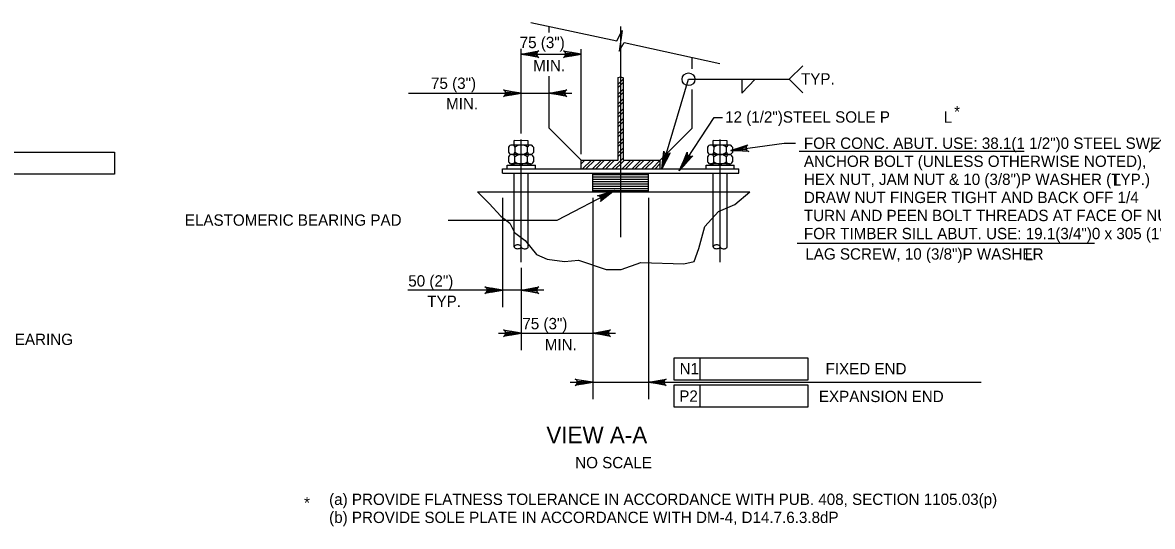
# Model space of a CAD drawing. Extents: x 638175 to 640495, y 294277 to 298435.
# Drawn here: x 639510.9 to 639809.5, y 298033.7 to 298167 of the extents above; entities that cross this region are included whole.
import ezdxf

# ---------------------------------------------------------------- set-up
doc = ezdxf.new("R2010")
doc.units = 0
for name, color, linetype in [('3', 7, 'Continuous'), ('4', 7, 'Continuous'), ('8', 7, 'Continuous')]:
    doc.layers.add(name, color=color, linetype=linetype)

msp = doc.modelspace()

# ---------------------------------------------------------------- linework, layer by layer
at = {"layer": '3'}
for p, q in [((639650.07, 298164.36), (639650.07, 298165.95)), ((639668.98, 298110.18), (639668.98, 298165.93)), ((639687.89, 298154.73), (639687.89, 298157.75)), ((639650.07, 298139.06), (639650.07, 298152.76)), ((639668.28, 298152.42), (639668.34, 298152.48)), ((639668.28, 298130.61), (639668.28, 298152.47)), ((639669.68, 298130.61), (639669.68, 298152.35)), ((639668.28, 298150.68), (639668.98, 298151.38)), ((639668.28, 298149.81), (639668.98, 298150.51)), ((639668.98, 298151.38), (639669.68, 298152.08)), ((639668.98, 298150.51), (639669.68, 298151.21)), ((639668.98, 298148.77), (639669.68, 298149.47)), ((639668.28, 298148.07), (639668.98, 298148.77)), ((639668.28, 298147.2), (639668.98, 298147.9)), ((639668.98, 298147.9), (639669.68, 298148.6)), ((639668.98, 298146.16), (639669.68, 298146.86)), ((639687.89, 298139.06), (639687.89, 298149.26)), ((639668.28, 298145.46), (639668.98, 298146.16)), ((639668.28, 298144.59), (639668.98, 298145.29)), ((639668.28, 298142.85), (639668.98, 298143.55)), ((639668.98, 298145.29), (639669.68, 298145.99)), ((639668.98, 298143.55), (639669.68, 298144.25)), ((639668.98, 298142.68), (639669.68, 298143.38)), ((639668.28, 298141.98), (639668.98, 298142.68)), ((639668.28, 298140.24), (639668.98, 298140.94)), ((639668.98, 298140.94), (639669.68, 298141.64)), ((639668.98, 298140.07), (639669.68, 298140.77)), ((639668.28, 298139.37), (639668.98, 298140.07)), ((639668.28, 298137.63), (639668.98, 298138.33)), ((639668.28, 298136.76), (639668.98, 298137.46)), ((639668.98, 298138.33), (639669.68, 298139.03)), ((639668.98, 298137.46), (639669.68, 298138.16)), ((639645.15, 298134.57), (639640.17, 298134.58)), ((639644.56, 298135.72), (639640.81, 298135.73)), ((639640.81, 298134.57), (639640.81, 298135.73)), ((639642.69, 298103.61), (639642.69, 298136.04)), ((639644.56, 298134.57), (639644.56, 298135.72)), ((639668.28, 298135.02), (639668.98, 298135.72)), ((639668.28, 298134.15), (639668.98, 298134.85)), ((639668.98, 298135.72), (639669.68, 298136.42)), ((639668.98, 298134.85), (639669.68, 298135.55)), ((639697.74, 298134.57), (639692.76, 298134.58)), ((639693.4, 298134.57), (639693.4, 298135.73)), ((639697.15, 298135.72), (639693.4, 298135.73)), ((639695.27, 298103.61), (639695.27, 298136.04)), ((639697.15, 298134.57), (639697.15, 298135.72)), ((639639.35, 298131.5), (639639.34, 298130.16)), ((639639.35, 298134), (639639.35, 298132.66)), ((639645.15, 298132.07), (639640.17, 298132.08)), ((639641.04, 298130.15), (639641.04, 298131.49)), ((639641.05, 298132.65), (639641.05, 298134)), ((639644.32, 298130.15), (639644.33, 298131.49)), ((639644.33, 298132.65), (639644.33, 298133.99)), ((639645.91, 298133.98), (639645.91, 298132.64)), ((639645.91, 298131.48), (639645.91, 298130.14)), ((639668.28, 298132.41), (639668.98, 298133.11)), ((639668.28, 298131.54), (639668.98, 298132.24)), ((639668.98, 298133.11), (639669.68, 298133.81)), ((639668.98, 298132.24), (639669.68, 298132.94)), ((639691.93, 298131.5), (639691.93, 298130.16)), ((639691.94, 298134), (639691.94, 298132.66)), ((639697.73, 298132.07), (639692.76, 298132.08)), ((639693.63, 298132.65), (639693.64, 298134)), ((639693.63, 298130.15), (639693.63, 298131.49)), ((639696.91, 298130.15), (639696.91, 298131.49)), ((639696.92, 298132.65), (639696.92, 298133.99)), ((639698.5, 298131.48), (639698.49, 298130.14)), ((639698.5, 298133.98), (639698.5, 298132.64)), ((639638.95, 298129.25), (639646.43, 298129.25)), ((639638.95, 298128.27), (639638.95, 298129.25)), ((639645.14, 298129.57), (639640.16, 298129.58)), ((639640.81, 298129.25), (639640.81, 298129.57)), ((639644.56, 298129.25), (639644.56, 298129.57)), ((639646.43, 298128.27), (639646.43, 298129.25)), ((639658.51, 298128.27), (639658.51, 298130.61)), ((639658.51, 298130.61), (639668.28, 298130.61)), ((639658.51, 298130.47), (639658.65, 298130.61)), ((639658.51, 298129.6), (639659.52, 298130.61)), ((639658.92, 298128.27), (639661.26, 298130.61)), ((639659.79, 298128.27), (639662.13, 298130.61)), ((639661.53, 298128.27), (639663.87, 298130.61)), ((639662.4, 298128.27), (639664.74, 298130.61)), ((639664.14, 298128.27), (639666.48, 298130.61)), ((639665.01, 298128.27), (639667.35, 298130.61)), ((639666.75, 298128.27), (639668.98, 298130.5)), ((639667.62, 298128.27), (639668.98, 298129.63)), ((639668.98, 298130.5), (639669.68, 298131.2)), ((639668.98, 298129.63), (639669.96, 298130.61)), ((639669.36, 298128.27), (639671.7, 298130.61)), ((639669.68, 298130.61), (639679.45, 298130.61)), ((639670.23, 298128.27), (639672.57, 298130.61)), ((639671.97, 298128.27), (639674.31, 298130.61)), ((639672.84, 298128.27), (639675.18, 298130.61)), ((639674.58, 298128.27), (639676.92, 298130.61)), ((639675.45, 298128.27), (639677.79, 298130.61)), ((639677.19, 298128.27), (639679.45, 298130.53)), ((639678.06, 298128.27), (639679.45, 298129.66)), ((639679.45, 298128.27), (639679.45, 298130.61)), ((639691.53, 298129.25), (639699.01, 298129.25)), ((639691.53, 298128.27), (639691.53, 298129.25)), ((639697.73, 298129.57), (639692.75, 298129.58)), ((639693.4, 298129.25), (639693.4, 298129.57)), ((639697.15, 298129.25), (639697.15, 298129.57)), ((639699.01, 298128.27), (639699.01, 298129.25)), ((639637.77, 298128.27), (639700.2, 298128.27)), ((639637.77, 298127.09), (639637.77, 298128.27)), ((639637.77, 298127.09), (639700.2, 298127.09)), ((639640.81, 298122.17), (639640.81, 298127.09)), ((639644.56, 298122.17), (639644.56, 298127.09)), ((639661.6, 298122.17), (639661.6, 298127.09)), ((639661.6, 298127.09), (639661.6, 298127.09)), ((639661.6, 298126.81), (639668.98, 298126.81)), ((639661.6, 298126.19), (639668.98, 298126.19)), ((639661.6, 298125.57), (639668.98, 298125.57)), ((639668.98, 298126.81), (639676.36, 298126.81)), ((639668.98, 298126.19), (639676.36, 298126.19)), ((639668.98, 298125.57), (639676.36, 298125.57)), ((639676.36, 298122.17), (639676.36, 298127.09)), ((639693.4, 298122.17), (639693.4, 298127.09)), ((639697.15, 298122.17), (639697.15, 298127.09)), ((639700.2, 298127.09), (639700.2, 298128.27)), ((639661.6, 298124.96), (639668.98, 298124.96)), ((639661.6, 298124.34), (639668.98, 298124.34)), ((639661.6, 298123.73), (639668.98, 298123.73)), ((639661.6, 298123.11), (639668.98, 298123.11)), ((639661.6, 298122.5), (639668.98, 298122.5)), ((639668.98, 298124.96), (639676.36, 298124.96)), ((639668.98, 298124.34), (639676.36, 298124.34)), ((639668.98, 298123.73), (639676.36, 298123.73)), ((639668.98, 298123.11), (639676.36, 298123.11)), ((639668.98, 298122.5), (639676.36, 298122.5)), ((639631.13, 298122.17), (639703.15, 298122.17)), ((639640.81, 298107.62), (639640.81, 298122.17)), ((639644.59, 298122.17), (639644.56, 298122.2)), ((639644.56, 298107.62), (639644.56, 298122.17)), ((639693.4, 298107.62), (639693.4, 298122.17)), ((639697.15, 298107.62), (639697.15, 298122.17))]:
    msp.add_line(p, q, dxfattribs=at)
for points in [[(639668.28, 298152.47), (639668.92, 298152.59), (639669.68, 298152.35)], [(639631.13, 298122.17), (639634.2, 298119.1), (639637.26, 298115.73), (639639.72, 298113.89), (639640.94, 298111.44), (639643.7, 298109.3), (639646.76, 298105.63), (639649.52, 298104.4), (639654.12, 298103.79), (639657.79, 298104.09), (639665.15, 298101.64), (639669.13, 298101.64), (639674.34, 298103.48), (639685.68, 298103.17), (639688.44, 298103.79), (639689.67, 298107.16), (639691.2, 298112.98), (639694.87, 298116.96), (639699.17, 298118.8), (639703.15, 298122.17)]]:
    msp.add_lwpolyline(points, dxfattribs=at)
for centre, radius, start, end in [((639640.2, 298133.67), 0.912, 88.0545, 158.5946), ((639640.2, 298133.67), 0.912, 21.1685, 88.0545), ((639642.69, 298131.96), 2.61, 50.9315, 128.8315), ((639645.12, 298133.74), 0.829, 17.3333, 162.4297), ((639692.79, 298133.67), 0.912, 88.0545, 158.5946), ((639692.79, 298133.67), 0.912, 21.1685, 88.0545), ((639695.27, 298131.96), 2.61, 50.9315, 128.8315), ((639697.71, 298133.74), 0.829, 17.3333, 162.4297), ((639640.2, 298132.99), 0.912, 201.1685, 271.7086), ((639640.19, 298131.16), 0.912, 88.0545, 158.5946), ((639640.2, 298132.99), 0.912, 271.7086, 338.5946), ((639640.19, 298131.16), 0.912, 21.1685, 88.0545), ((639642.68, 298129.46), 2.61, 50.9315, 128.8315), ((639642.69, 298134.68), 2.61, 230.9315, 308.8315), ((639645.12, 298132.89), 0.829, 197.3333, 342.4297), ((639645.12, 298131.24), 0.829, 17.3333, 162.4297), ((639692.78, 298131.16), 0.912, 88.0545, 158.5946), ((639692.79, 298132.99), 0.912, 201.1685, 271.7086), ((639692.79, 298132.99), 0.912, 271.7086, 338.5946), ((639692.78, 298131.16), 0.912, 21.1685, 88.0545), ((639695.28, 298134.68), 2.61, 230.9315, 308.8315), ((639695.27, 298129.46), 2.61, 50.9315, 128.8315), ((639697.7, 298131.24), 0.829, 17.3333, 162.4297), ((639697.71, 298132.89), 0.829, 197.3333, 342.4297), ((639640.19, 298130.49), 0.912, 201.1685, 271.7086), ((639640.19, 298130.49), 0.912, 271.7086, 338.5946), ((639642.69, 298132.18), 2.61, 230.9315, 308.8315), ((639645.11, 298130.39), 0.829, 197.3333, 342.4297), ((639692.78, 298130.49), 0.912, 201.1685, 271.7086), ((639692.78, 298130.49), 0.912, 271.7086, 338.5946), ((639695.27, 298132.18), 2.61, 230.9315, 308.8315), ((639697.7, 298130.39), 0.829, 197.3333, 342.4297), ((639641.09, 298107.64), 0.278, 142.0693, 180), ((639641.09, 298107.64), 0.278, 180, 217.9307), ((639641.41, 298107.4), 0.674, 117.9903, 142.0693), ((639641.61, 298107.01), 1.12, 102.4157, 117.9903), ((639641.75, 298106.39), 1.75, 90, 102.4157), ((639641.75, 298106.39), 1.75, 77.5843, 90), ((639641.89, 298107.01), 1.12, 62.0097, 77.5843), ((639642.1, 298107.4), 0.674, 37.9307, 62.0097), ((639642.41, 298107.64), 0.278, 0, 37.9307), ((639642.41, 298107.64), 0.278, 322.0693, 0), ((639642.96, 298107.62), 0.278, 180, 217.9307), ((639644.28, 298107.62), 0.278, 322.0693, 360), ((639644.28, 298107.62), 0.278, 360, 1.757), ((639693.68, 298107.64), 0.278, 142.0693, 180), ((639693.68, 298107.64), 0.278, 180, 217.9307), ((639693.99, 298107.4), 0.674, 117.9903, 142.0693), ((639694.2, 298107.01), 1.12, 102.4157, 117.9903), ((639694.34, 298106.39), 1.75, 90, 102.4157), ((639694.34, 298106.39), 1.75, 77.5843, 90), ((639694.48, 298107.01), 1.12, 62.0097, 77.5843), ((639694.68, 298107.4), 0.674, 37.9307, 62.0097), ((639695, 298107.64), 0.278, 0, 37.9307), ((639695, 298107.64), 0.278, 322.0693, 0), ((639695.55, 298107.62), 0.278, 180, 217.9307), ((639696.87, 298107.62), 0.278, 322.0693, 360), ((639696.87, 298107.62), 0.278, 360, 1.757), ((639641.41, 298107.89), 0.674, 217.9307, 242.0097), ((639641.61, 298108.28), 1.12, 242.0097, 257.5843), ((639641.75, 298108.9), 1.75, 257.5843, 270), ((639641.75, 298108.9), 1.75, 270, 282.4157), ((639641.89, 298108.28), 1.12, 282.4157, 297.9903), ((639642.1, 298107.89), 0.674, 297.9903, 322.0693), ((639643.28, 298107.87), 0.674, 217.9307, 242.0097), ((639643.48, 298108.26), 1.12, 242.0097, 257.5843), ((639643.62, 298108.88), 1.75, 257.5843, 270), ((639643.62, 298108.88), 1.75, 270, 282.4157), ((639643.76, 298108.26), 1.12, 282.4157, 297.9903), ((639643.97, 298107.87), 0.674, 297.9903, 322.0693), ((639693.99, 298107.89), 0.674, 217.9307, 242.0097), ((639694.2, 298108.28), 1.12, 242.0097, 257.5843), ((639694.34, 298108.9), 1.75, 257.5843, 270), ((639694.34, 298108.9), 1.75, 270, 282.4157), ((639694.48, 298108.28), 1.12, 282.4157, 297.9903), ((639694.68, 298107.89), 0.674, 297.9903, 322.0693), ((639695.86, 298107.87), 0.674, 217.9307, 242.0097), ((639696.07, 298108.26), 1.12, 242.0097, 257.5843), ((639696.21, 298108.88), 1.75, 257.5843, 270), ((639696.21, 298108.88), 1.75, 270, 282.4157), ((639696.35, 298108.26), 1.12, 282.4157, 297.9903), ((639696.55, 298107.87), 0.674, 297.9903, 322.0693)]:
    msp.add_arc(centre, radius, start, end, dxfattribs=at)
at = {"layer": '4'}
for p, q in [((639645.23, 298166.98), (639667.92, 298162.15)), ((639667.92, 298162.15), (639669.41, 298164.9)), ((639669.41, 298164.9), (639668.55, 298159.44)), ((639668.55, 298159.44), (639669.92, 298161.71)), ((639669.92, 298161.71), (639695.22, 298156.13)), ((639642.69, 298137.61), (639642.69, 298160.06)), ((639642.69, 298158.61), (639658.51, 298158.61)), ((639658.51, 298132.17), (639658.51, 298159.94)), ((639713.47, 298151.98), (639717.09, 298155.55)), ((639679.89, 298128.27), (639686.9, 298151.98)), ((639686.9, 298151.98), (639713.47, 298151.98)), ((639701.01, 298148.31), (639704.54, 298151.98)), ((639701.01, 298151.98), (639701.01, 298148.31)), ((639713.47, 298151.98), (639717.09, 298148.4)), ((639612.86, 298148.28), (639656.07, 298148.28)), ((639684.76, 298128.27), (639693.68, 298141.88)), ((639693.68, 298141.88), (639695.92, 298141.88)), ((639698.1, 298133.09), (639712.15, 298135.06)), ((639712.15, 298135.06), (639715.15, 298135.06)), ((639808.64, 298132.73), (639812.48, 298136.57)), ((639493.67, 298132.65), (639535.19, 298132.65)), ((639535.19, 298132.65), (639535.19, 298126.88)), ((639716.16, 298132.91), (639775.64, 298132.91)), ((639535.19, 298126.88), (639493.67, 298126.88)), ((639667.35, 298122.57), (639652.14, 298114.57)), ((639637.77, 298120.6), (639637.77, 298091.68)), ((639661.6, 298120.6), (639661.6, 298067.29)), ((639676.36, 298120.6), (639676.36, 298067.29)), ((639652.14, 298114.57), (639623.39, 298114.57)), ((639715.62, 298108.6), (639794.17, 298108.6)), ((639642.69, 298102.04), (639642.69, 298080.28)), ((639648.66, 298096.18), (639612.71, 298096.18)), ((639636.72, 298084.78), (639667.6, 298084.78)), ((639683.12, 298078.31), (639718.42, 298078.31)), ((639683.12, 298072.4), (639683.12, 298078.31)), ((639690.01, 298072.4), (639690.01, 298078.31)), ((639718.42, 298078.31), (639718.42, 298072.4)), ((639655.63, 298071.79), (639764.22, 298071.79)), ((639718.42, 298072.4), (639683.12, 298072.4)), ((639683.12, 298071.12), (639718.42, 298071.12)), ((639683.12, 298065.22), (639683.12, 298071.12)), ((639690.01, 298065.22), (639690.01, 298071.12)), ((639718.42, 298071.12), (639718.42, 298065.22)), ((639718.42, 298065.22), (639683.12, 298065.22))]:
    msp.add_line(p, q, dxfattribs=at)
for points in [[(639642.69, 298158.61), (639647.35, 298159.48), (639646.99, 298159.23), (639646.8, 298158.92), (639646.75, 298158.61), (639646.8, 298158.3), (639646.99, 298157.98), (639647.35, 298157.73), (639642.69, 298158.61), (639646.99, 298157.98), (639646.8, 298158.3), (639642.69, 298158.61), (639646.75, 298158.61), (639646.8, 298158.92), (639642.69, 298158.61), (639646.99, 298159.23)], [(639658.51, 298158.61), (639653.85, 298157.73), (639654.21, 298157.98), (639654.39, 298158.3), (639654.45, 298158.61), (639654.39, 298158.92), (639654.21, 298159.23), (639653.85, 298159.48), (639658.51, 298158.61), (639654.21, 298159.23), (639654.39, 298158.92), (639658.51, 298158.61), (639654.45, 298158.61), (639654.39, 298158.3), (639658.51, 298158.61), (639654.21, 298157.98)], [(639642.69, 298148.28), (639638.03, 298147.4), (639638.38, 298147.65), (639638.57, 298147.96), (639638.62, 298148.28), (639638.57, 298148.59), (639638.38, 298148.9), (639638.03, 298149.15), (639642.69, 298148.28), (639638.38, 298148.9), (639638.57, 298148.59), (639642.69, 298148.28), (639638.62, 298148.28), (639638.57, 298147.96), (639642.69, 298148.28), (639638.38, 298147.65)], [(639650.07, 298148.28), (639654.73, 298149.15), (639654.37, 298148.9), (639654.19, 298148.59), (639654.13, 298148.28), (639654.19, 298147.96), (639654.37, 298147.65), (639654.73, 298147.4), (639650.07, 298148.28), (639654.37, 298147.65), (639654.19, 298147.96), (639650.07, 298148.28), (639654.13, 298148.28), (639654.19, 298148.59), (639650.07, 298148.28), (639654.37, 298148.9)], [(639698.1, 298133.09), (639702.59, 298134.6), (639702.27, 298134.31), (639702.13, 298133.97), (639702.12, 298133.66), (639702.22, 298133.35), (639702.44, 298133.07), (639702.83, 298132.87), (639698.1, 298133.09), (639702.44, 298133.07), (639702.22, 298133.35), (639698.1, 298133.09), (639702.12, 298133.66), (639702.13, 298133.97), (639698.1, 298133.09), (639702.27, 298134.31)], [(639679.89, 298128.27), (639680.38, 298132.99), (639680.51, 298132.57), (639680.76, 298132.31), (639681.04, 298132.17), (639681.36, 298132.13), (639681.71, 298132.22), (639682.05, 298132.49), (639679.89, 298128.27), (639681.71, 298132.22), (639681.36, 298132.13), (639679.89, 298128.27), (639681.04, 298132.17), (639680.76, 298132.31), (639679.89, 298128.27), (639680.51, 298132.57)], [(639684.76, 298128.27), (639686.58, 298132.65), (639686.59, 298132.21), (639686.75, 298131.88), (639686.98, 298131.67), (639687.27, 298131.54), (639687.64, 298131.52), (639688.04, 298131.69), (639684.76, 298128.27), (639687.64, 298131.52), (639687.27, 298131.54), (639684.76, 298128.27), (639686.98, 298131.67), (639686.75, 298131.88), (639684.76, 298128.27), (639686.59, 298132.21)], [(639667.35, 298122.57), (639663.63, 298119.62), (639663.83, 298120.01), (639663.85, 298120.37), (639663.75, 298120.67), (639663.56, 298120.93), (639663.25, 298121.12), (639662.82, 298121.17), (639667.35, 298122.57), (639663.25, 298121.12), (639663.56, 298120.93), (639667.35, 298122.57), (639663.75, 298120.67), (639663.85, 298120.37), (639667.35, 298122.57), (639663.83, 298120.01)], [(639637.77, 298096.18), (639633.11, 298095.31), (639633.46, 298095.56), (639633.65, 298095.87), (639633.7, 298096.18), (639633.65, 298096.49), (639633.46, 298096.81), (639633.11, 298097.06), (639637.77, 298096.18), (639633.46, 298096.81), (639633.65, 298096.49), (639637.77, 298096.18), (639633.7, 298096.18), (639633.65, 298095.87), (639637.77, 298096.18), (639633.46, 298095.56)], [(639642.69, 298096.18), (639647.35, 298097.06), (639646.99, 298096.81), (639646.8, 298096.49), (639646.75, 298096.18), (639646.8, 298095.87), (639646.99, 298095.56), (639647.35, 298095.31), (639642.69, 298096.18), (639646.99, 298095.56), (639646.8, 298095.87), (639642.69, 298096.18), (639646.75, 298096.18), (639646.8, 298096.49), (639642.69, 298096.18), (639646.99, 298096.81)], [(639642.69, 298084.78), (639638.03, 298083.91), (639638.38, 298084.15), (639638.57, 298084.47), (639638.62, 298084.78), (639638.57, 298085.09), (639638.38, 298085.4), (639638.03, 298085.65), (639642.69, 298084.78), (639638.38, 298085.4), (639638.57, 298085.09), (639642.69, 298084.78), (639638.62, 298084.78), (639638.57, 298084.47), (639642.69, 298084.78), (639638.38, 298084.15)], [(639661.6, 298084.78), (639666.26, 298085.65), (639665.9, 298085.4), (639665.72, 298085.09), (639665.66, 298084.78), (639665.72, 298084.47), (639665.9, 298084.15), (639666.26, 298083.91), (639661.6, 298084.78), (639665.9, 298084.15), (639665.72, 298084.47), (639661.6, 298084.78), (639665.66, 298084.78), (639665.72, 298085.09), (639661.6, 298084.78), (639665.9, 298085.4)], [(639661.6, 298071.79), (639656.94, 298070.92), (639657.3, 298071.17), (639657.48, 298071.48), (639657.54, 298071.79), (639657.48, 298072.1), (639657.3, 298072.42), (639656.94, 298072.66), (639661.6, 298071.79), (639657.3, 298072.42), (639657.48, 298072.1), (639661.6, 298071.79), (639657.54, 298071.79), (639657.48, 298071.48), (639661.6, 298071.79), (639657.3, 298071.17)], [(639676.36, 298071.79), (639681.02, 298072.66), (639680.66, 298072.42), (639680.48, 298072.1), (639680.42, 298071.79), (639680.48, 298071.48), (639680.66, 298071.17), (639681.02, 298070.92), (639676.36, 298071.79), (639680.66, 298071.17), (639680.48, 298071.48), (639676.36, 298071.79), (639680.42, 298071.79), (639680.48, 298072.1), (639676.36, 298071.79), (639680.66, 298072.42)]]:
    msp.add_lwpolyline(points, dxfattribs=at)
for points in [[(639645.69, 298159.11), (639645.69, 298158.11), (639642.69, 298158.61)], [(639655.51, 298159.11), (639655.51, 298158.11), (639658.51, 298158.61)], [(639639.69, 298148.78), (639639.69, 298147.78), (639642.69, 298148.28)], [(639653.07, 298148.78), (639653.07, 298147.78), (639650.07, 298148.28)], [(639701.15, 298133.01), (639701.01, 298134), (639698.11, 298133.09)], [(639681.23, 298131.02), (639680.27, 298131.32), (639679.83, 298128.32)], [(639685.65, 298130.49), (639686.49, 298129.95), (639684.43, 298127.71)], [(639634.77, 298096.68), (639634.77, 298095.68), (639637.77, 298096.18)], [(639645.69, 298096.68), (639645.69, 298095.68), (639642.69, 298096.18)], [(639639.69, 298085.28), (639639.69, 298084.28), (639642.69, 298084.78)], [(639664.6, 298085.28), (639664.6, 298084.28), (639661.6, 298084.78)], [(639658.6, 298072.29), (639658.6, 298071.29), (639661.6, 298071.79)], [(639679.36, 298072.29), (639679.36, 298071.29), (639676.36, 298071.79)]]:
    msp.add_lwpolyline(points, close=True, dxfattribs=at)
msp.add_circle((639686.9, 298151.98), 1.69, dxfattribs=at)
for centre in [(639642.96, 298107.64), (639695.55, 298107.64)]:
    msp.add_arc(centre, 0.278, 180, 182.0078, dxfattribs=at)
at = {"layer": '8'}
for p, q in [((639658.51, 298130.61), (639650.07, 298139.06)), ((639679.45, 298130.61), (639687.89, 298139.06))]:
    msp.add_line(p, q, dxfattribs=at)

# ---------------------------------------------------------------- texts
at = {"layer": '4'}
for s, height, p in [('75 (3")', 3, (639642.29, 298160.22)), ('MIN.', 3, (639645.83, 298154.11)), ('75 (3")', 3, (639618.85, 298149.42)), ('TYP.', 3, (639716.62, 298150.58)), ('MIN.', 3, (639622.83, 298144.03)), ('12 (1/2")STEEL SOLE P', 3, (639696.58, 298140.5)), ('L', 3, (639754.36, 298140.45)), ('*', 3, (639757.1, 298141.9)), ('FOR CONC. ABUT. USE: 38.1(1 1/2")0 STEEL SWEDGE', 3, (639717.4, 298133.56)), ('ANCHOR BOLT (UNLESS OTHERWISE NOTED), ', 3, (639717.4, 298128.78)), ('HEX NUT, JAM NUT & 10 (3/8")P WASHER (TYP.)', 3, (639717.4, 298124)), ('L', 3, (639799.01, 298123.83)), ('DRAW NUT FINGER TIGHT AND BACK OFF 1/4', 3, (639717.4, 298119.22)), ('TURN AND PEEN BOLT THREADS AT FACE OF NUTS.', 3, (639717.4, 298114.44)), ('ELASTOMERIC BEARING PAD', 3, (639553.78, 298113.22)), ('FOR TIMBER SILL ABUT. USE: 19.1(3/4")0 x 305 (1\'-0") LONG ', 3, (639717.4, 298109.66)), ('LAG SCREW, 10 (3/8")P WASHER', 3, (639717.77, 298104.25)), ('L', 3, (639775.78, 298104.08)), ('50 (2")', 3, (639612.84, 298097.12)), ('TYP.', 3, (639617.85, 298091.72)), ('75 (3")', 3, (639642.99, 298085.83)), ('L BEARING', 3, (639502.83, 298081.66)), ('MIN.', 3, (639648.91, 298080.28)), ('N1', 3, (639684.55, 298073.9)), ('FIXED END', 3, (639723.12, 298073.89)), ('P2', 3, (639684.46, 298066.65)), ('EXPANSION END', 3, (639721.35, 298066.56)), ('VIEW A-A', 4.429, (639649.34, 298055.64)), ('NO SCALE', 3, (639656.95, 298049.04)), ('(a) PROVIDE FLATNESS TOLERANCE IN ACCORDANCE WITH PUB. 408, SECTION 1105.03(p)', 3, (639591.92, 298039.34)), ('*', 3, (639585.29, 298038.41)), ('(b) PROVIDE SOLE PLATE IN ACCORDANCE WITH DM-4, D14.7.6.3.8dP', 3, (639591.92, 298034.56))]:
    msp.add_text(s, height=height, dxfattribs=at).set_placement(p)

doc.saveas('drawing.dxf')
